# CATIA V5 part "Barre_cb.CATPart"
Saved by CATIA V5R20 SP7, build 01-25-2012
Part number: Barre_cb
Bounding box of the stored display mesh (mm): x 15 to 30, y -5.999 to 55.999, z 80.61 to 179.197
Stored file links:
  G:\bon\Nouveau dossier\Barre_cb.CATPart
  G:\bon\Nouveau dossier\cgirerd.CATProduct
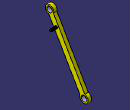
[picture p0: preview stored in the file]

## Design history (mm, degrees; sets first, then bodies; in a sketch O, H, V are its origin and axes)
External parameters (linked from other documents)
  External.longueur_1 = 100 mm
  External.Ratio_point_ellipse = 0.8
Set1
  Point1 "B": linked copy from another document
  Point2 "C": linked copy from another document
Body1 (main body)
  Sketch1 on yz-plane, origin (0, 0, 0), H (0, 1, 0), V (0, 0, 1)
    arc A1 centre (0, 173.2051) radius 6 from (5.7002, 171.3321) to (-1.228, 167.3321) ccw
    point P1 (0, 173.2051)
    reference projected point E1 (0, 173.2051) from Point1
    arc A2 centre (50, 86.6025) radius 6 from (44.2998, 88.4755) to (51.228, 92.4755) ccw
    point P2 (50, 86.6025)
    reference projected point E2 (50, 86.6025) from Point2
    line L1 (-1.228, 167.3321) -> (44.2998, 88.4755)
    line L2 (5.7002, 171.3321) -> (51.228, 92.4755)
    radius A1 = 6
    radius A2 = 6
    distance L1 L2 = 8
    distance L2 P1 = 4
    distance L1 P2 = 4
    coincidence: P1 E1, P2 E2
  Pad1: profile Sketch1, direction (1, 0, 0), length 20, opposite side length -15
  Sketch2 on end face of Pad1, origin (20, 0, 0), H (0, 1, 0), V (0, 0, 1)
    circle A1 centre (50, 86.6025) radius 4
    point P1 (50, 86.6025)
    reference projected point E1 (50, 86.6025) from Point2
    radius A1 = 4
    coincidence: P1 E1
  Pocket1: profile Sketch2, direction (-1, 0, 0), length 5
  Sketch3 on end face of Pad1, origin (20, 0, 0), H (0, 1, 0), V (0, 0, 1)
    circle A1 centre (0, 173.2051) radius 4
    point P1 (0, 173.2051)
    reference projected point E1 (0, 173.2051) from Point1
    radius A1 = 4
    coincidence: P1 E1
  Pocket2: profile Sketch3, direction (-1, 0, 0), length 5
  Sketch4 on end face of Pad1, origin (20, 0, 0), H (0, 1, 0), V (0, 0, 1)
    circle A1 centre (10, 155.8846) radius 2
    point P1 (10, 155.8846)
    reference projected line E1 (-1.228, 167.3321) -> (44.2998, 88.4755) from edge [face of Pad1 from Sketch1.L1 | end face of Pad1]
    reference projected point E2 (50, 86.6025) from Point2
    distance P1 E1 = 4
    radius A1 = 2
    distance P1 E2 = 80 {= External.longueur_1 *External.Ratio_point_ellipse}
  Pad2: profile Sketch4, direction (1, 0, 0), length 10
  Chamfer1: length 3, angle 30, on edge [face of Pad2 from Sketch4.A1 | end face of Pad2]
